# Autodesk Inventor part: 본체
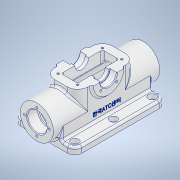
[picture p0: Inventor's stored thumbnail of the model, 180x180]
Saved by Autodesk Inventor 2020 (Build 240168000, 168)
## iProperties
Created: 2024-06
Part Number: 본체
Material: 알루미늄 6061
Document SubType Name: Modeling
Designer: oem
Density: 2.7 g/cm^3
Appearance: 알루미늄 - 평지
Mass: 556.265 g
Surface Area: 613.691 cm^2
Volume: 206.024 cm^3
Author: oem
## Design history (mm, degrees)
sketch "스케치1"
  geometry: C1 r 24 at (0, 0); 1 further point
  constraints: 1 centre point, 1 coincident
  dimensions: "d0" = 48 diameter of C1
extrude "돌출1" new body sketch "스케치1" stored distance "d1" = 154; taper "d2" = 0 deg
node "작업 평면1"
sketch "스케치2"
  geometry: L1 (-24, 66)-(24, 66); L2 (24, 66)-(24, -66); L3 (24, -66)-(-24, -66); L4 (-24, -66)-(-24, 66); L5 (-24, 66)-(24, -66); L6 (24, 66)-(-24, -66); 1 further point
  constraints: 12 end point, 2 midpoint, 2 parallel, 1 horizontal, 1 perpendicular
  dimensions: "d4" = 48 distance of L2.end L3.end; "d5" = 132 distance of L1.end L2.end
node "작업 평면2"
sketch "스케치3"
  geometry: L1 (24, -42)-(-24, -42); L2 (-24, -42)-(-24, 42); L3 (-24, 42)-(24, 42); L4 (24, 42)-(24, -42); L5 (24, -42)-(-24, 42); L6 (-24, -42)-(24, 42); 1 further point
  constraints: 12 end point, 2 midpoint, 2 parallel, 1 horizontal, 1 perpendicular
  dimensions: "d9" = 48 distance of L2.end L3.end; "d10" = 84 distance of L1.end L2.end
extrude "돌출3" join sketch "스케치3" distance "d11" = 59; taper "d12" = 0 deg
sketch "스케치4"
  geometry: L1 (84, 0)-(0, 0) reference; L2 (20, 0)-(64, 0); A1 r 22 centre (42, 0) between (20, 0) and (64, 0); 1 further point
  constraints: 2 end point, 2 point on circle, 2 point on line, 1 centre point, 1 collinear, 1 midpoint
  dimensions: "d13" = 44 diameter of A1
extrude "돌출4" join sketch "스케치4" distance "d14" = 3; taper "d15" = 0 deg
extrude "돌출5" join sketch "스케치2" stored distance "d18" = 59; taper "d19" = 0 deg
sketch "스케치7"
  geometry: L1 (-44, -66)-(44, -66); L2 (44, -66)-(44, 66); L3 (44, 66)-(-44, 66); L4 (-44, 66)-(-44, -66); L5 (-44, -66)-(44, 66); L6 (44, -66)-(-44, 66); 1 further point
  constraints: 12 end point, 2 midpoint, 2 parallel, 1 horizontal, 1 perpendicular
  dimensions: "d20" = 88 distance of L3.end L2.end; "d21" = 132 distance of L2.end L1.end
extrude "돌출6" join sketch "스케치7" distance "d22" = 10; taper "d23" = 0 deg
sketch "스케치9"
  geometry: A1 r 24 centre (0, 0) between (15.875, -18) and (-15.875, -18) reference; 1 further point
  constraints: 1 coincident
hole "구멍1" sketch "스케치9" at (0, 0) diameter "d28" = 22; stored, may be unused: countersink angle "d32" = 90 deg, drill point angle "d34" = 118 deg; dims "d29" = 6, "d30" = 28, "d31" = 15, "d33" = 8
sketch "스케치10"
  geometry: L1 (-12, -30)-(12, -30); L2 (12, -30)-(12, 30); L3 (12, 30)-(-12, 30); L4 (-12, 30)-(-12, -30); L5 (-12, -30)-(12, 30); L6 (12, -30)-(-12, 30); 1 further point
  constraints: 12 end point, 2 midpoint, 2 parallel, 1 horizontal, 1 perpendicular
  dimensions: "d35" = 24 distance of L3.end L2.end; "d36" = 60 distance of L2.end L1.end
extrude "돌출8" cut sketch "스케치10" stored distance "d37" = 42; taper "d38" = 0 deg
sketch "스케치11"
  geometry: A1 r 22 centre (42, 0) between (20, 0) and (64, 0) reference; 2 further points
  constraints: 1 coincident
hole "구멍2" sketch "스케치11" at (42, 0) diameter "d39" = 20; stored, may be unused: countersink angle "d43" = 90 deg, drill point angle "d45" = 0 deg; dims "d40" = 6, "d41" = 24, "d42" = 10, "d44" = 8
chamfer "모따기1" distance "d46" = 1; stored, may be unused: second distance "d47" = 2, angle "d48" = 45 deg
sketch "스케치12"
  geometry: C1 r 14 at (0, 0) reference; 1 further point
  constraints: 1 vertical alignment
  dimensions: "d49" = 18 distance of C1.centre point (0, 18)
hole "구멍3" sketch "스케치12" at (0, 18) diameter "d50" = 3.242; stored, may be unused: countersink angle "d54" = 90 deg, drill point angle "d56" = 118 deg; dims "d51" = 8, "d52" = 24, "d53" = 10, "d55" = 10
fillet "모깎기1" dims "d60" = 3
sketch "스케치13"
  geometry: L1 (-18, 0)-(-18, -28); L2 (44, -28)-(-44, -28) reference; L3 (18, 0)-(18, -28); L4 (18, -28)-(-18, -28); A1 r 18 centre (0, 0) between (18, 0) and (-18, 0); 2 further points
  constraints: 6 end point, 2 point on circle, 2 tangent, 2 vertical, 1 centre point, 1 coincident, 1 perpendicular, 1 point on line
  dimensions: "d110" = 18 radius of A1
extrude "돌출9" cut sketch "스케치13" stored distance "d63" = 120; taper "d64" = 0 deg
sketch "스케치14"
  geometry: L1 (42, 0)-(42, -16); L2 (42, 0)-(30.686, -11.314); L3 (42, 0)-(53.314, -11.314); A1 r 13 centre (42, 0) between (29, 0) and (55, 0) reference; A2 r 22 centre (42, 0) between (20, 0) and (64, 0) reference; A3 r 16 centre (42, 0) between (42, -16) and (30.686, -11.314); 3 further points
  constraints: 6 end point, 3 coincident, 3 point on circle, 1 centre point, 1 vertical alignment
  dimensions: "d66" = 32 diameter of A3; "d67" = 45 deg angle of L1 L2; "d69" = 45 deg angle of L1 L3
hole "구멍4" sketch "스케치14" at (30.686, -11.314), (53.314, -11.314) diameter "d70" = 3.242; stored, may be unused: countersink angle "d74" = 90 deg, drill point angle "d76" = 118 deg; dims "d71" = 8, "d72" = 24, "d73" = 10, "d75" = 10
sketch "스케치15"
  geometry: L1 (-14, 32)-(14, 32); L2 (14, 32)-(14, -32); L3 (14, -32)-(-14, -32); L4 (-14, -32)-(-14, 32); L5 (-14, 32)-(14, -32); L6 (14, 32)-(-14, -32); 5 further points
  constraints: 12 end point, 4 coincident, 2 midpoint, 2 parallel, 1 horizontal, 1 perpendicular
  dimensions: "d77" = 28 distance of L2.end L3.end; "d78" = 64 distance of L1.end L2.end
hole "구멍5" sketch "스케치15" at (-14, 32), (14, 32), (14, -32), (-14, -32) diameter "d79" = 3.242; stored, may be unused: countersink angle "d83" = 90 deg, drill point angle "d85" = 118 deg; dims "d80" = 8, "d81" = 24, "d82" = 10, "d84" = 10
fillet "모깎기4" dims "d86" = 10
sketch "스케치16"
  geometry: L1 (44, 56)-(44, -56) reference; L2 (44, 0)-(-44, 0); L3 (-44, -56)-(-44, 56) reference; A1 r 10 centre (-34, 56) between (-34, 66) and (-44, 56) reference; A2 r 10 centre (-34, -56) between (-44, -56) and (-34, -66) reference; 4 further points
  constraints: 2 coincident, 2 end point, 2 midpoint, 1 point on line, 1 vertical alignment
hole "구멍6" sketch "스케치16" at (-34, 56), (-34, 0), (-34, -56) diameter "d87" = 6.6; stored, may be unused: countersink angle "d91" = 90 deg, drill point angle "d93" = 0 deg; dims "d88" = 8, "d89" = 11, "d90" = 6.6, "d92" = 10
fillet "모깎기6" dims "d95" = 15
fillet "모깎기7" dims "d96" = 3
fillet "모깎기8" dims "d97" = 3
fillet "모깎기9" dims "d98" = 3
fillet "모깎기10" dims "d99" = 3
fillet "모깎기11" dims "d100" = 3
chamfer "모따기2" distance "d101" = 1; stored, may be unused: second distance "d102" = 2, angle "d103" = 45 deg
fillet "모깎기12" dims "d104" = 3
node "작업 평면3"
sketch "스케치17"
  geometry: L1 (83, -28)-(-29, -28) reference; 2 further points
  constraints: 1 vertical alignment, 1 other
  dimensions: "d106" = 20 distance from line of L1 point (27, -8)
feature "엠보싱1" sketch "스케치17" dims "d107" = 0.5, "d108" = 0
fillet "모깎기13" dims "d111" = 3
chamfer "모따기3" distance "d112" = 1; stored, may be unused: second distance "d113" = 2, angle "d114" = 45 deg
fillet "모깎기14" dims "d115" = 0.3
node "솔리드1"
mirror "미러1"
mirror "미러2"
mirror "미러3"
pattern_circular "원형 패턴1" dims angle "d58" = 360 deg
mirror "미러4"
mirror "미러5"
mirror "미러6"
feature "A9D066F2-1C7D-4E18-AEED-F7BC21143FA4" dims "d28" = 22, "d29" = 6, "d30" = 28, "d31" = 15, "d32" = 90 deg, "d33" = 8, "d34" = 118 deg
other parameters: "d3" = -28, "d105" = 5
